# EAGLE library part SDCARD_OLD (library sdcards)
SD card connector KINGFONT SDCMF-10915W010
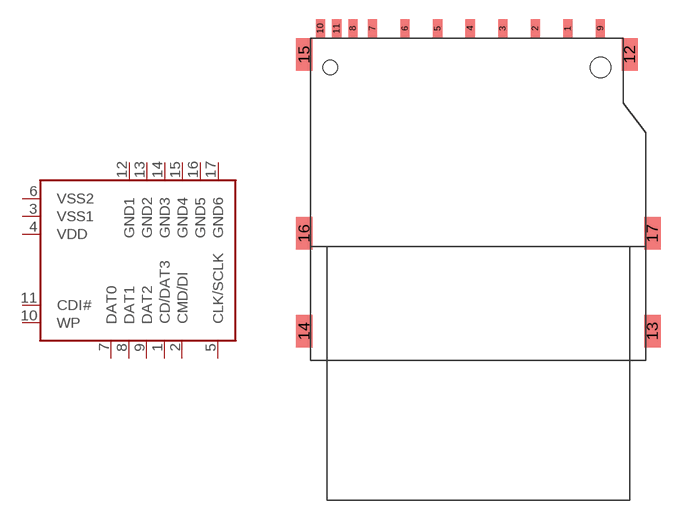
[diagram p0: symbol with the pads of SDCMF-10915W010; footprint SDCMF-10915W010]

Designator prefix -

## SDCARD_OLDVAR1  [SDCMF-10915W010]
1  CD/DAT3
2  CMD/DI
3  VSS1  pwr
4  VDD  pwr
5  CLK/SCLK
6  VSS2  pwr
7  DAT0
8  DAT1
9  DAT2
10  WP  out
11  CDI#  out
12  GND1  pwr
13  GND2  pwr
14  GND3  pwr
15  GND4  pwr
16  GND5  pwr
17  GND6  pwr

## Footprint SDCMF-10915W010 (pad centres in mm)
SD card connector KINGFONT SDCMF-10915W010
smd 0.711 x 1.422: 1 7.366,13.462; 2 4.826,13.462; 3 2.286,13.462; 4 -0.254,13.462; 5 -2.794,13.462; 6 -5.334,13.462; 7 -7.874,13.462; 8 -9.398,13.462; 9 9.906,13.462; 10 -11.938,13.462; 11 -10.668,13.462
smd 1.27 x 2.54: 12 12.192,11.43; 13 13.97,-10.16; 14 -13.208,-10.16; 15 -13.208,11.43; 16 -13.208,-2.54; 17 13.97,-2.54
hole 1.6 at 9.906,10.414
hole 1.1 at -11.176,10.414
